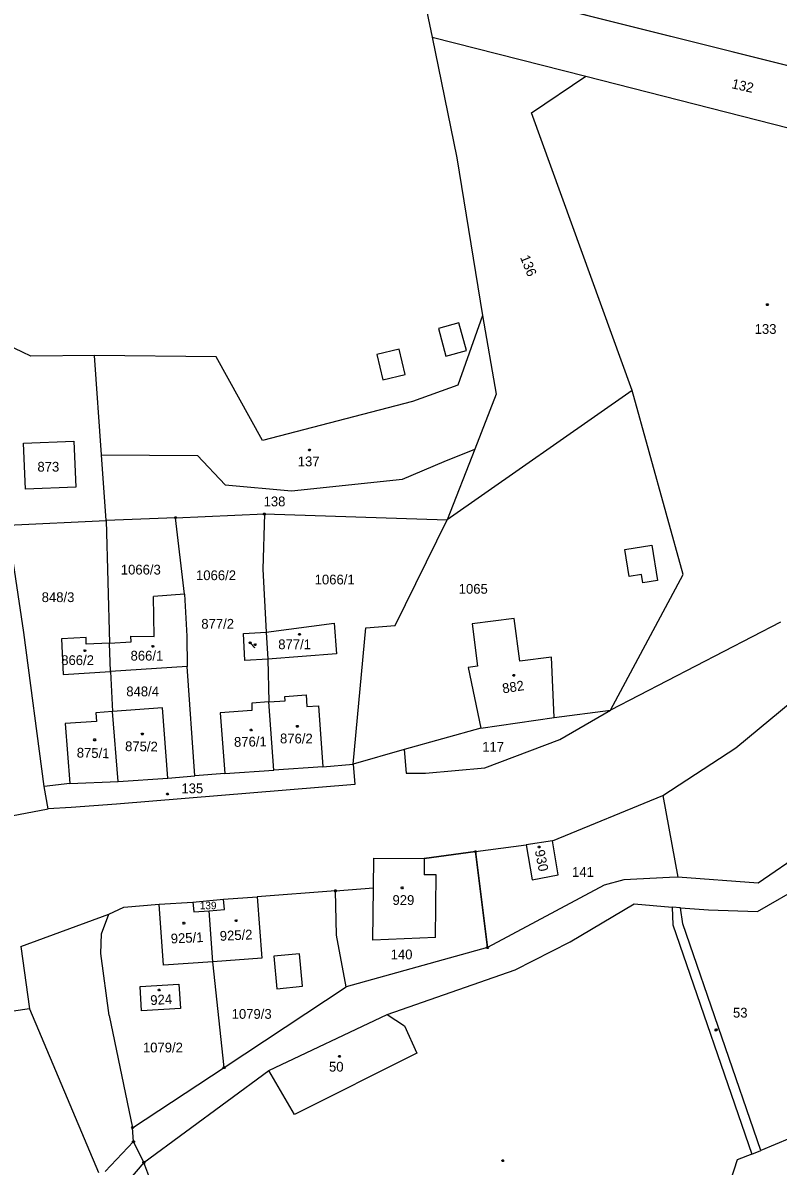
# Model space of a CAD drawing. Extents: x -841286 to -834997, y -1020681 to -1017810.
# Drawn here: x -838632.6 to -838501.3, y -1019173.8 to -1018975 of the extents above; entities that cross this region are included whole.
import ezdxf

# ---------------------------------------------------------------- set-up
doc = ezdxf.new("R2010")
doc.units = 0
for name, color, linetype in [('NERES_HRA', 7, 'Continuous'), ('NERES_SET', 7, 'Continuous'), ('OVNE_POP', 7, 'Continuous'), ('OVNE_PRE', 7, 'Continuous'), ('OVNE_SET', 7, 'Continuous'), ('OVNI_PRE', 7, 'Continuous'), ('OVNI_SET', 7, 'Continuous')]:
    doc.layers.add(name, color=color, linetype=linetype)

msp = doc.modelspace()

# ---------------------------------------------------------------- linework, layer by layer
at = {"layer": 'NERES_HRA'}
for points in [[(-838590.52, -1019060.22), (-838590.43, -1019060.37), (-838590.52, -1019060.52), (-838590.7, -1019060.52), (-838590.79, -1019060.37), (-838590.7, -1019060.22)], [(-838605.97, -1019060.89), (-838605.88, -1019061.04), (-838605.97, -1019061.19), (-838606.15, -1019061.19), (-838606.24, -1019061.04), (-838606.15, -1019060.89)], [(-838553.81, -1019118.94), (-838553.72, -1019119.09), (-838553.81, -1019119.24), (-838553.99, -1019119.24), (-838554.08, -1019119.09), (-838553.99, -1019118.94)], [(-838578.13, -1019125.76), (-838578.04, -1019125.91), (-838578.13, -1019126.06), (-838578.31, -1019126.06), (-838578.4, -1019125.91), (-838578.31, -1019125.76)], [(-838551.74, -1019135.61), (-838551.65, -1019135.76), (-838551.74, -1019135.91), (-838551.92, -1019135.91), (-838552.01, -1019135.76), (-838551.92, -1019135.61)], [(-838597.53, -1019156.49), (-838597.44, -1019156.64), (-838597.53, -1019156.79), (-838597.71, -1019156.79), (-838597.8, -1019156.64), (-838597.71, -1019156.49)], [(-838613.42, -1019166.95), (-838613.33, -1019167.1), (-838613.42, -1019167.25), (-838613.6, -1019167.25), (-838613.69, -1019167.1), (-838613.6, -1019166.95)]]:
    msp.add_lwpolyline(points, close=True, dxfattribs=at)
at = {"layer": 'NERES_SET'}
for p, q in [((-838592.26, -1019083.66), (-838593.08, -1019082.78)), ((-838512.32, -1019150.26), (-838512.05, -1019150.08))]:
    msp.add_line(p, q, dxfattribs=at)
for points in [[(-838593.12, -1019082.61), (-838592.95, -1019082.66), (-838592.91, -1019082.83), (-838593.04, -1019082.95), (-838593.21, -1019082.9), (-838593.25, -1019082.73)], [(-838511.88, -1019150.07), (-838511.95, -1019150.23), (-838512.12, -1019150.24), (-838512.22, -1019150.09), (-838512.15, -1019149.93), (-838511.98, -1019149.92)]]:
    msp.add_lwpolyline(points, close=True, dxfattribs=at)
at = {"layer": 'OVNE_POP'}
for points in [[(-838503.07, -1019023.86), (-838502.98, -1019024.01), (-838503.07, -1019024.16), (-838503.25, -1019024.16), (-838503.34, -1019024.01), (-838503.25, -1019023.86)], [(-838582.69, -1019049.13), (-838582.6, -1019049.28), (-838582.69, -1019049.43), (-838582.87, -1019049.43), (-838582.96, -1019049.28), (-838582.87, -1019049.13)], [(-838607.36, -1019108.9), (-838607.27, -1019109.05), (-838607.36, -1019109.2), (-838607.54, -1019109.2), (-838607.63, -1019109.05), (-838607.54, -1019108.9)], [(-838577.47, -1019154.52), (-838577.38, -1019154.67), (-838577.47, -1019154.82), (-838577.65, -1019154.82), (-838577.74, -1019154.67), (-838577.65, -1019154.52)], [(-838549.08, -1019172.66), (-838548.99, -1019172.81), (-838549.08, -1019172.96), (-838549.26, -1019172.96), (-838549.35, -1019172.81), (-838549.26, -1019172.66)]]:
    msp.add_lwpolyline(points, close=True, dxfattribs=at)
at = {"layer": 'OVNE_SET'}
for p, q in [((-838483.95, -1018986.37), (-838555.51, -1018968.42)), ((-838563.02, -1018969.86), (-838561.46, -1018977.47)), ((-838561.46, -1018977.47), (-838557.16, -1018998.47)), ((-838561.46, -1018977.47), (-838534.71, -1018984.27)), ((-838544.19, -1018990.62), (-838534.71, -1018984.27)), ((-838534.71, -1018984.27), (-838485.02, -1018996.92)), ((-838526.67, -1019038.89), (-838544.19, -1018990.62)), ((-838557.16, -1018998.47), (-838552.69, -1019025.9)), ((-838631.21, -1019032.96), (-838643.38, -1019027.06)), ((-838552.69, -1019025.9), (-838557, -1019037.98)), ((-838552.69, -1019025.9), (-838550.28, -1019039.55)), ((-838620.12, -1019032.83), (-838631.21, -1019032.96)), ((-838618.91, -1019050.1), (-838620.12, -1019032.83)), ((-838599, -1019033.04), (-838620.12, -1019032.83)), ((-838590.93, -1019047.58), (-838599, -1019033.04)), ((-838557, -1019037.98), (-838564.88, -1019040.82)), ((-838526.67, -1019038.89), (-838558.84, -1019061.38)), ((-838517.82, -1019070.9), (-838526.67, -1019038.89)), ((-838564.88, -1019040.82), (-838590.93, -1019047.58)), ((-838550.28, -1019039.55), (-838554.03, -1019049.12)), ((-838632.48, -1019048.07), (-838623.71, -1019047.72)), ((-838632.16, -1019056.06), (-838632.48, -1019048.07)), ((-838623.71, -1019047.72), (-838623.38, -1019055.7)), ((-838618.11, -1019061.54), (-838618.91, -1019050.1)), ((-838618.91, -1019050.1), (-838602.25, -1019050.24)), ((-838602.25, -1019050.24), (-838597.43, -1019055.29)), ((-838559.34, -1019051.27), (-838554.03, -1019049.12)), ((-838554.03, -1019049.12), (-838558.84, -1019061.38)), ((-838566.58, -1019054.33), (-838559.34, -1019051.27)), ((-838585.86, -1019056.36), (-838566.58, -1019054.33)), ((-838623.38, -1019055.7), (-838632.16, -1019056.06)), ((-838597.43, -1019055.29), (-838585.86, -1019056.36)), ((-838606.06, -1019061.04), (-838590.61, -1019060.37)), ((-838590.61, -1019060.37), (-838590.88, -1019070)), ((-838590.61, -1019060.37), (-838558.84, -1019061.38)), ((-838635.18, -1019062.3), (-838618.11, -1019061.54)), ((-838632.41, -1019081), (-838635.18, -1019062.3)), ((-838606.06, -1019061.04), (-838618.11, -1019061.54)), ((-838618.11, -1019061.54), (-838617.51, -1019082.82)), ((-838604.47, -1019074.31), (-838606.06, -1019061.04)), ((-838567.89, -1019079.78), (-838558.84, -1019061.38)), ((-838590.88, -1019070), (-838590.28, -1019080.93)), ((-838530.43, -1019094.52), (-838517.82, -1019070.9)), ((-838604.47, -1019074.31), (-838609.87, -1019074.72)), ((-838609.79, -1019081.71), (-838609.87, -1019074.72)), ((-838604.47, -1019074.31), (-838604.1, -1019081.6)), ((-838547.15, -1019078.57), (-838554.48, -1019079.5)), ((-838546.21, -1019085.98), (-838547.15, -1019078.57)), ((-838590.28, -1019080.93), (-838578.46, -1019079.38)), ((-838578.46, -1019079.38), (-838578.08, -1019084.68)), ((-838575.17, -1019103.88), (-838572.96, -1019080.19)), ((-838572.96, -1019080.19), (-838567.89, -1019079.78)), ((-838554.48, -1019079.5), (-838553.55, -1019086.87)), ((-838500.9, -1019079.2), (-838530.43, -1019094.52)), ((-838628.87, -1019107.78), (-838632.41, -1019081)), ((-838621.58, -1019081.88), (-838625.9, -1019082.09)), ((-838625.9, -1019082.09), (-838625.61, -1019088.27)), ((-838621.56, -1019083.04), (-838621.58, -1019081.88)), ((-838617.51, -1019082.82), (-838613.75, -1019082.62)), ((-838613.75, -1019082.62), (-838613.81, -1019081.61)), ((-838613.81, -1019081.61), (-838609.79, -1019081.71)), ((-838604.1, -1019081.6), (-838604.01, -1019086.93)), ((-838594.25, -1019081.14), (-838590.28, -1019080.93)), ((-838594.01, -1019085.86), (-838594.25, -1019081.14)), ((-838590.28, -1019080.93), (-838590.03, -1019085.65)), ((-838617.51, -1019082.82), (-838621.56, -1019083.04)), ((-838617.37, -1019087.76), (-838617.51, -1019082.82)), ((-838578.08, -1019084.68), (-838590.03, -1019085.65)), ((-838590.03, -1019085.65), (-838594.01, -1019085.86)), ((-838590.03, -1019085.65), (-838589.82, -1019093.06)), ((-838540.67, -1019085.27), (-838546.21, -1019085.98)), ((-838540.23, -1019095.75), (-838540.67, -1019085.27)), ((-838625.61, -1019088.27), (-838617.37, -1019087.76)), ((-838604.01, -1019086.93), (-838617.37, -1019087.76)), ((-838617.37, -1019087.76), (-838616.99, -1019094.74)), ((-838602.72, -1019105.91), (-838604.01, -1019086.93)), ((-838553.55, -1019086.87), (-838555.17, -1019087.07)), ((-838555.17, -1019087.07), (-838553, -1019097.6)), ((-838508.62, -1019101.06), (-838492.37, -1019087.53)), ((-838587.04, -1019092.09), (-838583.36, -1019091.84)), ((-838586.99, -1019092.88), (-838587.04, -1019092.09)), ((-838583.36, -1019091.84), (-838583.22, -1019093.86)), ((-838608.31, -1019094.09), (-838616.99, -1019094.74)), ((-838607.41, -1019106.31), (-838608.31, -1019094.09)), ((-838592.76, -1019094.58), (-838598.29, -1019094.96)), ((-838589.82, -1019093.06), (-838592.81, -1019093.25)), ((-838592.81, -1019093.25), (-838592.76, -1019094.58)), ((-838589.82, -1019093.06), (-838586.99, -1019092.88)), ((-838588.96, -1019104.93), (-838589.82, -1019093.06)), ((-838583.22, -1019093.86), (-838581.18, -1019093.72)), ((-838581.18, -1019093.72), (-838580.45, -1019104.35)), ((-838540.23, -1019095.75), (-838530.43, -1019094.52)), ((-838539.22, -1019099.59), (-838530.43, -1019094.52)), ((-838619.79, -1019096.47), (-838625.25, -1019096.8)), ((-838616.99, -1019094.74), (-838619.9, -1019094.95)), ((-838619.9, -1019094.95), (-838619.79, -1019096.47)), ((-838616.03, -1019106.89), (-838616.99, -1019094.74)), ((-838598.29, -1019094.96), (-838597.48, -1019105.51)), ((-838553, -1019097.6), (-838540.23, -1019095.75)), ((-838625.25, -1019096.8), (-838624.45, -1019107.23)), ((-838553, -1019097.6), (-838566.28, -1019101.36)), ((-838552.29, -1019104.53), (-838539.22, -1019099.59)), ((-838566.28, -1019101.36), (-838575.17, -1019103.88)), ((-838566.28, -1019101.36), (-838565.96, -1019105.45)), ((-838521.34, -1019109.32), (-838508.62, -1019101.06)), ((-838580.45, -1019104.35), (-838588.96, -1019104.93)), ((-838580.45, -1019104.35), (-838575.17, -1019103.88)), ((-838575.17, -1019103.88), (-838574.85, -1019107.41)), ((-838562.61, -1019105.43), (-838552.29, -1019104.53)), ((-838616.03, -1019106.89), (-838607.41, -1019106.31)), ((-838607.41, -1019106.31), (-838602.72, -1019105.91)), ((-838597.48, -1019105.51), (-838602.72, -1019105.91)), ((-838597.48, -1019105.51), (-838588.96, -1019104.93)), ((-838565.96, -1019105.45), (-838562.61, -1019105.43)), ((-838624.45, -1019107.23), (-838628.87, -1019107.78)), ((-838628.17, -1019111.65), (-838628.87, -1019107.78)), ((-838624.45, -1019107.23), (-838616.03, -1019106.89)), ((-838574.85, -1019107.41), (-838616.3, -1019110.83)), ((-838540.49, -1019117.24), (-838521.34, -1019109.32)), ((-838521.34, -1019109.32), (-838518.7, -1019123.56)), ((-838642.85, -1019114.42), (-838628.17, -1019111.65)), ((-838624.21, -1019111.43), (-838628.17, -1019111.65)), ((-838616.3, -1019110.83), (-838624.21, -1019111.43)), ((-838553.9, -1019119.09), (-838545.1, -1019117.91)), ((-838540.49, -1019117.24), (-838545.1, -1019117.91)), ((-838545.1, -1019117.91), (-838544.03, -1019124.01)), ((-838539.52, -1019123.15), (-838540.49, -1019117.24)), ((-838495.22, -1019118.02), (-838504.75, -1019124.59)), ((-838571.62, -1019125.4), (-838571.55, -1019120.22)), ((-838571.55, -1019120.22), (-838562.81, -1019120.31)), ((-838562.81, -1019120.31), (-838562.82, -1019123.14)), ((-838553.9, -1019119.09), (-838562.81, -1019120.31)), ((-838551.83, -1019135.76), (-838553.9, -1019119.09)), ((-838504.89, -1019129.51), (-838486.15, -1019118.69)), ((-838560.72, -1019123.15), (-838562.82, -1019123.14)), ((-838560.83, -1019134.03), (-838560.72, -1019123.15)), ((-838544.03, -1019124.01), (-838539.52, -1019123.15)), ((-838528.13, -1019123.98), (-838531.51, -1019124.94)), ((-838520.16, -1019123.61), (-838528.13, -1019123.98)), ((-838518.7, -1019123.56), (-838520.16, -1019123.61)), ((-838504.75, -1019124.59), (-838518.7, -1019123.56)), ((-838578.22, -1019125.91), (-838591.86, -1019126.96)), ((-838578.22, -1019125.91), (-838571.62, -1019125.4)), ((-838578.08, -1019133.61), (-838578.22, -1019125.91)), ((-838571.73, -1019134.47), (-838571.62, -1019125.4)), ((-838531.51, -1019124.94), (-838551.83, -1019135.76)), ((-838615.02, -1019128.74), (-838608.89, -1019128.2)), ((-838608.89, -1019128.2), (-838603.05, -1019127.85)), ((-838608.12, -1019138.86), (-838608.89, -1019128.2)), ((-838603.05, -1019127.85), (-838597.71, -1019127.38)), ((-838603.05, -1019127.85), (-838602.89, -1019129.55)), ((-838597.71, -1019127.38), (-838591.86, -1019126.96)), ((-838597.54, -1019129.17), (-838597.71, -1019127.38)), ((-838591.86, -1019126.96), (-838591.02, -1019137.62)), ((-838537.46, -1019134.77), (-838526.33, -1019128.18)), ((-838526.33, -1019128.18), (-838519.73, -1019128.72)), ((-838632.96, -1019135.58), (-838617.66, -1019129.98)), ((-838618.91, -1019133.36), (-838617.66, -1019129.98)), ((-838617.66, -1019129.98), (-838615.02, -1019128.74)), ((-838602.89, -1019129.55), (-838600.22, -1019129.36)), ((-838600.22, -1019129.36), (-838597.54, -1019129.17)), ((-838599.58, -1019138.24), (-838600.22, -1019129.36)), ((-838518.24, -1019128.84), (-838519.73, -1019128.72)), ((-838519.73, -1019128.72), (-838519.58, -1019131.84)), ((-838517.87, -1019131.64), (-838518.24, -1019128.84)), ((-838518.24, -1019128.84), (-838513.39, -1019129.24)), ((-838513.39, -1019129.24), (-838504.89, -1019129.51)), ((-838519.58, -1019131.84), (-838505.87, -1019171.67)), ((-838504.29, -1019171.04), (-838517.87, -1019131.64)), ((-838619.05, -1019136.78), (-838618.91, -1019133.36)), ((-838576.4, -1019142.61), (-838578.08, -1019133.61)), ((-838560.83, -1019134.03), (-838571.73, -1019134.47)), ((-838632.96, -1019135.58), (-838631.42, -1019146.42)), ((-838551.83, -1019135.76), (-838576.4, -1019142.61)), ((-838546.99, -1019139.63), (-838537.46, -1019134.77)), ((-838617.6, -1019147.61), (-838619.05, -1019136.78)), ((-838599.58, -1019138.24), (-838608.12, -1019138.86)), ((-838591.02, -1019137.62), (-838599.58, -1019138.24)), ((-838597.62, -1019156.64), (-838599.58, -1019138.24)), ((-838569.26, -1019147.42), (-838546.99, -1019139.63)), ((-838612.22, -1019142.55), (-838605.46, -1019142.14)), ((-838605.46, -1019142.14), (-838605.2, -1019146.39)), ((-838611.96, -1019146.8), (-838612.22, -1019142.55)), ((-838597.62, -1019156.64), (-838576.4, -1019142.61)), ((-838576.4, -1019142.61), (-838576.4, -1019142.61)), ((-838631.42, -1019146.42), (-838653.72, -1019149.68)), ((-838631.42, -1019146.42), (-838619.46, -1019174.91)), ((-838617.6, -1019147.61), (-838613.51, -1019167.1)), ((-838605.2, -1019146.39), (-838611.96, -1019146.8)), ((-838589.82, -1019157.17), (-838569.26, -1019147.42)), ((-838569.26, -1019147.42), (-838566.26, -1019149.37)), ((-838566.26, -1019149.37), (-838564.1, -1019154.13)), ((-838564.1, -1019154.13), (-838585.39, -1019164.78)), ((-838613.51, -1019167.1), (-838597.62, -1019156.64)), ((-838611.56, -1019173.14), (-838589.82, -1019157.17)), ((-838585.39, -1019164.78), (-838589.82, -1019157.17)), ((-838490.88, -1019165.46), (-838504.29, -1019171.04)), ((-838613.36, -1019169.5), (-838613.51, -1019167.1)), ((-838611.56, -1019173.14), (-838613.36, -1019169.5)), ((-838505.87, -1019171.67), (-838508.43, -1019172.69)), ((-838505.87, -1019171.67), (-838504.29, -1019171.04)), ((-838600.81, -1019201.29), (-838611.56, -1019173.14)), ((-838508.43, -1019172.69), (-838512.25, -1019184.55))]:
    msp.add_line(p, q, dxfattribs=at)
at = {"layer": 'OVNI_PRE'}
for points in [[(-838584.41, -1019081.17), (-838584.32, -1019081.32), (-838584.41, -1019081.47), (-838584.59, -1019081.47), (-838584.68, -1019081.32), (-838584.59, -1019081.17)], [(-838621.72, -1019084), (-838621.63, -1019084.15), (-838621.72, -1019084.3), (-838621.9, -1019084.3), (-838621.99, -1019084.15), (-838621.9, -1019084)], [(-838609.9, -1019083.26), (-838609.81, -1019083.41), (-838609.9, -1019083.56), (-838610.08, -1019083.56), (-838610.17, -1019083.41), (-838610.08, -1019083.26)], [(-838592.13, -1019082.96), (-838592.04, -1019083.11), (-838592.13, -1019083.26), (-838592.31, -1019083.26), (-838592.4, -1019083.11), (-838592.31, -1019082.96)], [(-838547.15, -1019088.31), (-838547.06, -1019088.46), (-838547.15, -1019088.61), (-838547.33, -1019088.61), (-838547.42, -1019088.46), (-838547.33, -1019088.31)], [(-838611.73, -1019098.51), (-838611.64, -1019098.66), (-838611.73, -1019098.81), (-838611.91, -1019098.81), (-838612, -1019098.66), (-838611.91, -1019098.51)], [(-838592.82, -1019097.78), (-838592.73, -1019097.93), (-838592.82, -1019098.08), (-838593, -1019098.08), (-838593.09, -1019097.93), (-838593, -1019097.78)], [(-838584.78, -1019097.16), (-838584.69, -1019097.31), (-838584.78, -1019097.46), (-838584.96, -1019097.46), (-838585.05, -1019097.31), (-838584.96, -1019097.16)], [(-838620.02, -1019099.5), (-838619.93, -1019099.65), (-838620.02, -1019099.8), (-838620.2, -1019099.8), (-838620.29, -1019099.65), (-838620.2, -1019099.5)], [(-838542.74, -1019118.12), (-838542.65, -1019118.27), (-838542.74, -1019118.42), (-838542.92, -1019118.42), (-838543.01, -1019118.27), (-838542.92, -1019118.12)], [(-838566.58, -1019125.24), (-838566.49, -1019125.39), (-838566.58, -1019125.54), (-838566.76, -1019125.54), (-838566.85, -1019125.39), (-838566.76, -1019125.24)], [(-838604.51, -1019131.38), (-838604.42, -1019131.53), (-838604.51, -1019131.68), (-838604.69, -1019131.68), (-838604.78, -1019131.53), (-838604.69, -1019131.38)], [(-838595.44, -1019130.95), (-838595.35, -1019131.1), (-838595.44, -1019131.25), (-838595.62, -1019131.25), (-838595.71, -1019131.1), (-838595.62, -1019130.95)], [(-838608.81, -1019142.98), (-838608.72, -1019143.13), (-838608.81, -1019143.28), (-838608.99, -1019143.28), (-838609.08, -1019143.13), (-838608.99, -1019142.98)]]:
    msp.add_lwpolyline(points, close=True, dxfattribs=at)
at = {"layer": 'OVNI_SET'}
for p, q in [((-838556.78, -1019027.17), (-838560.36, -1019028.15)), ((-838560.36, -1019028.15), (-838559.05, -1019032.96)), ((-838555.46, -1019031.97), (-838556.78, -1019027.17)), ((-838567.2, -1019031.75), (-838571.06, -1019032.67)), ((-838571.06, -1019032.67), (-838570.01, -1019037.06)), ((-838566.15, -1019036.14), (-838567.2, -1019031.75)), ((-838559.05, -1019032.96), (-838555.46, -1019031.97)), ((-838570.01, -1019037.06), (-838566.15, -1019036.14)), ((-838527.96, -1019066.54), (-838523.26, -1019065.79)), ((-838527.21, -1019071.24), (-838527.96, -1019066.54)), ((-838523.26, -1019065.79), (-838522.28, -1019071.96)), ((-838525.03, -1019070.89), (-838527.21, -1019071.24)), ((-838524.8, -1019072.35), (-838525.03, -1019070.89)), ((-838522.28, -1019071.96), (-838524.8, -1019072.35)), ((-838562.81, -1019120.31), (-838562.81, -1019120.31)), ((-838584.51, -1019136.85), (-838588.98, -1019137.27)), ((-838588.98, -1019137.27), (-838588.45, -1019142.93)), ((-838583.98, -1019142.51), (-838584.51, -1019136.85)), ((-838588.45, -1019142.93), (-838583.98, -1019142.51)), ((-838618.31, -1019174.72), (-838613.36, -1019169.5)), ((-838611.56, -1019173.14), (-838616.49, -1019178.87))]:
    msp.add_line(p, q, dxfattribs=at)
for points in [[(-838382.4, -1018842.66), (-838387.4, -1018854.73), (-838400.4, -1018885.65), (-838411.01, -1018908.85), (-838442.62, -1018985.96), (-838450.34, -1018999.55), (-838452.31, -1019003.07), (-838458.62, -1018998.65), (-838483.95, -1018986.37), (-838555.51, -1018968.42)], [(-838562.81, -1019120.31), (-838553.9, -1019119.09), (-838551.83, -1019135.76), (-838576.4, -1019142.61)]]:
    msp.add_lwpolyline(points, dxfattribs=at)
for points in [[(-838613.37, -1019169.67), (-838613.52, -1019169.59), (-838613.51, -1019169.41), (-838613.35, -1019169.33), (-838613.2, -1019169.41), (-838613.21, -1019169.59)], [(-838611.73, -1019173.13), (-838611.64, -1019172.98), (-838611.47, -1019172.99), (-838611.39, -1019173.15), (-838611.48, -1019173.3), (-838611.65, -1019173.29)]]:
    msp.add_lwpolyline(points, close=True, dxfattribs=at)

# ---------------------------------------------------------------- texts
at = {"layer": 'NERES_SET'}
for s, p in [('877/2', (-838601.57, -1019080.33)), ('53', (-838509.14, -1019147.95))]:
    msp.add_text(s, height=1.7, dxfattribs=at).set_placement(p)
at = {"layer": 'OVNE_PRE'}
for s, rotation, p in [('132', 347.327, (-838509.47, -1018986.34)), ('136', 291.8074, (-838546.18, -1019015.75)), ('882', 8.9954, (-838549.11, -1019091.59)), ('876/2', 359.7029, (-838587.89, -1019100.26)), ('875/2', 359.2445, (-838614.83, -1019101.61)), ('876/1', 0.974, (-838595.87, -1019100.87)), ('875/1', 358.7289, (-838623.24, -1019102.73)), ('930', 281.1504, (-838543.6, -1019118.93)), ('925/1', 2.6929, (-838606.84, -1019135.07)), ('925/2', 2.6929, (-838598.32, -1019134.61)), ('924', 3.6096, (-838610.38, -1019145.79))]:
    msp.add_text(s, height=1.7, rotation=rotation, dxfattribs=at).set_placement(p)
for s, height, p in [('133', 1.7, (-838505.37, -1019029.07)), ('137', 1.7, (-838584.8, -1019052.09)), ('873', 1.7, (-838630.06, -1019053.02)), ('138', 1.7, (-838590.74, -1019059.05)), ('1066/3', 1.7, (-838615.56, -1019070.91)), ('1066/2', 1.7, (-838602.49, -1019071.89)), ('1066/1', 1.7, (-838581.86, -1019072.63)), ('1065', 1.7, (-838556.82, -1019074.25)), ('848/3', 1.7, (-838629.32, -1019075.7)), ('877/1', 1.7, (-838588.19, -1019083.89)), ('866/1', 1.7, (-838613.87, -1019085.87)), ('877/2', 0.1, (-838592.49, -1019083.66)), ('866/2', 1.7, (-838625.92, -1019086.65)), ('848/4', 1.7, (-838614.61, -1019092.08)), ('117', 1.7, (-838552.73, -1019101.71)), ('135', 1.7, (-838605.03, -1019108.94)), ('141', 1.7, (-838537.12, -1019123.48)), ('139', 1.3, (-838601.83, -1019129.11)), ('929', 1.7, (-838568.33, -1019128.36)), ('140', 1.7, (-838568.65, -1019137.81)), ('1079/3', 1.7, (-838596.29, -1019148.16)), ('53', 0.1, (-838512.4, -1019150.26)), ('1079/2', 1.7, (-838611.72, -1019154)), ('50', 1.7, (-838579.37, -1019157.34))]:
    msp.add_text(s, height=height, dxfattribs=at).set_placement(p)

doc.saveas('drawing.dxf')
